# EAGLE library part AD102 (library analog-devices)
ANALOG DEVICES
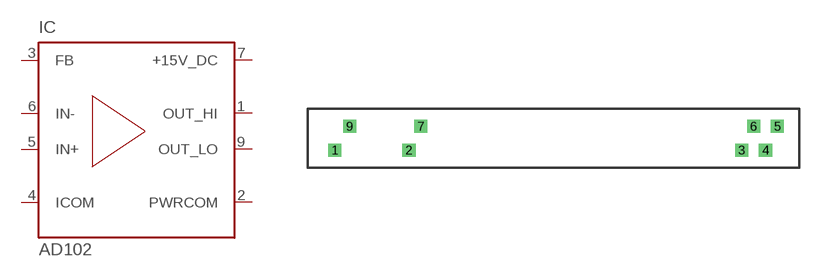
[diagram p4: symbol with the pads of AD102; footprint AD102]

Designator prefix IC

## AD102 (OC_FARNELL: unknown; OC_NEWARK: unknown)  [AD102]
1  OUT_HI  out
2  PWRCOM  out
3  FB  in
4  ICOM  pwr
5  IN+  in
6  IN-  in
7  +15V_DC  out
9  OUT_LO  out

## Footprint AD102 (pad centres in mm)
8 lead Package
drill 0.813 pad 1.397 square: 1 -23.368,-1.27; 2 -15.443,-1.27; 3 20.117,-1.27; 4 22.657,-1.27; 5 23.927,1.27; 6 21.387,1.27; 7 -14.173,1.27; 9 -21.793,1.27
